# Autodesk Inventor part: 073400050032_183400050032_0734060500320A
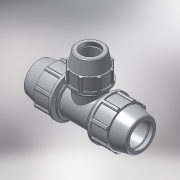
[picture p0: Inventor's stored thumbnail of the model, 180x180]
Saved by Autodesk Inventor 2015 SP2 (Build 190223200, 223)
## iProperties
Created: 2017-02
Part Number: 073400050032_183400050032_0734060500320A
Material: PVC-Piping
Description: PLASSON REDUCING TEE 50-32-50
Document SubType Name: Modeling
Designer: KIM
Mass: 92.6774 g
Surface Area: 199.44 cm^2
Volume: 66.1981 cm^3
Density: 1.4 g/cm^3
Appearance: Smooth - White
Author: Кирилл
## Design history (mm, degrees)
derived "07340.ipt"
feature "Solid1::07340.ipt"
feature "Solid2::07340.ipt"
tag "TaggingFeature1"
body "Solid1"
other parameters: "d4" = 9.58333, "d5" = 32.2, "d7" = 96, "d11" = 3.83333, "d13" = 120 deg, "d15" = 12 deg, "d16" = 83.52, "d18" = 2.5, "d19" = 35 deg, "d20" = 17.5 deg, "d21" = 89.28, "d23" = 0, "d25" = 360 deg, "d27" = 1.92, "d33" = 1, "d42" = 41.4, "d43" = 2.88, "d46" = 1.5, "d67" = 72, "d76" = 32, "d77" = 64, "d78" = 12 deg, "d79" = 117, "d80" = 120 deg, "d81" = 44.8, "d82" = 9.75, "d87" = 3.9, "d89" = 29.25, "d90" = 35.1, "d96" = 19.16667, "d98" = 59.52, "d99" = 35 deg, "d100" = 17.5 deg, "d102" = 0, "d103" = 1.28, "d107" = 360 deg, "d109" = 0.96, "d112" = 1.6, "d113" = 4.26667, "d114" = 0, "d118" = 55.68, "d126" = 45, "d127" = 93, "d131" = 4.68, "d132" = 28.8, "d133" = 67, "d135" = 0, "d138" = 4.6, "d143" = 0, "d148" = 48, "d168" = 45, "d170" = 0, "d171" = 32, "d173" = 0, "d175" = 0, "d176" = 4.26667, "d177" = 0, "E_" = 96, "A_" = 117, "l_" = 93, "E_1" = 64, "l_1" = 67, "d_1" = 32
